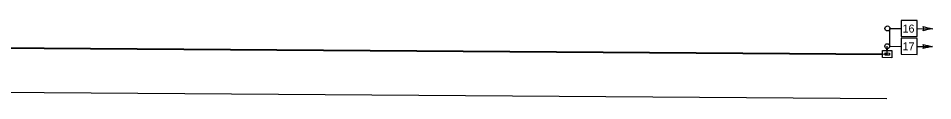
# Model space of a CAD drawing. Extents: x 1802372 to 1804337, y 572813 to 574117.
# Drawn here: x 1803965.8 to 1804336.9, y 573830 to 573861.6 of the extents above; entities that cross this region are included whole.
import ezdxf

# ---------------------------------------------------------------- set-up
doc = ezdxf.new("R2010")
doc.units = 0
for name, color, linetype in [('DSN_DRFT_DNC', 7, 'Continuous'), ('DSN_TRAF_Permanent Signal', 7, 'Continuous'), ('S_PRIMARY_CTL', 7, 'Continuous')]:
    doc.layers.add(name, color=color, linetype=linetype)

msp = doc.modelspace()

# ---------------------------------------------------------------- linework, layer by layer
at = {"layer": 'DSN_DRFT_DNC'}
for p, q in [((1803580.64, 573853.09), (1804318.42, 573847.97)), ((1804318.42, 573847.97), (1804318.44, 573851.16)), ((1803568.31, 573835.18), (1804318.29, 573829.97))]:
    msp.add_line(p, q, dxfattribs=at)
at = {"layer": 'DSN_TRAF_Permanent Signal'}
for p, q in [((1804319.44, 573851.15), (1804319.49, 573858.37)), ((1804319.49, 573858.37), (1804324.09, 573858.33)), ((1804330.59, 573858.3), (1804336.88, 573858.26)), ((1804319.44, 573851.15), (1804324.04, 573851.11)), ((1804330.54, 573851.09), (1804336.83, 573851.04))]:
    msp.add_line(p, q, dxfattribs=at)
for points in [[(1804330.57, 573855.05), (1804330.61, 573861.55), (1804324.11, 573861.6), (1804324.07, 573855.1)], [(1804330.51, 573847.84), (1804330.56, 573854.34), (1804324.06, 573854.38), (1804324.01, 573847.88)], [(1804320.28, 573846.5), (1804316.53, 573846.53), (1804316.55, 573849.44), (1804320.3, 573849.42)], [(1804319.29, 573847.51), (1804317.54, 573847.52), (1804317.55, 573848.44), (1804319.3, 573848.42)]]:
    msp.add_lwpolyline(points, close=True, dxfattribs=at)
for centre in [(1804318.49, 573858.37), (1804318.44, 573851.16)]:
    msp.add_circle(centre, 1, dxfattribs=at)
for centre, radius, start, end in [((1804331.61, 573858.29), 1.63, 327.7416, 31.4363), ((1804341.08, 573829.09), 29.47, 98.1973, 105.9354), ((1804341.5, 573887.36), 29.47, 253.2425, 260.9806), ((1804331.56, 573851.08), 1.63, 327.7548, 31.4494), ((1804341.04, 573821.87), 29.47, 98.2104, 105.9485), ((1804341.44, 573880.15), 29.47, 253.2557, 260.9938)]:
    msp.add_arc(centre, radius, start, end, dxfattribs=at)
at = {"layer": 'S_PRIMARY_CTL'}
for p, q in [((1803582.51, 573853.21), (1804316.54, 573848.11)), ((1803582.51, 573852.96), (1804316.54, 573847.86)), ((1804318.3, 573849.43), (1804318.31, 573850.17)), ((1804318.55, 573849.43), (1804318.56, 573850.16))]:
    msp.add_line(p, q, dxfattribs=at)

# ---------------------------------------------------------------- texts
at = {"layer": 'DSN_TRAF_Permanent Signal'}
for s, p in [('16', (1804324.64, 573856.72)), ('17', (1804324.64, 573849.5))]:
    msp.add_text(s, height=3.25, rotation=359.6021, dxfattribs=at).set_placement(p)

doc.saveas('drawing.dxf')
